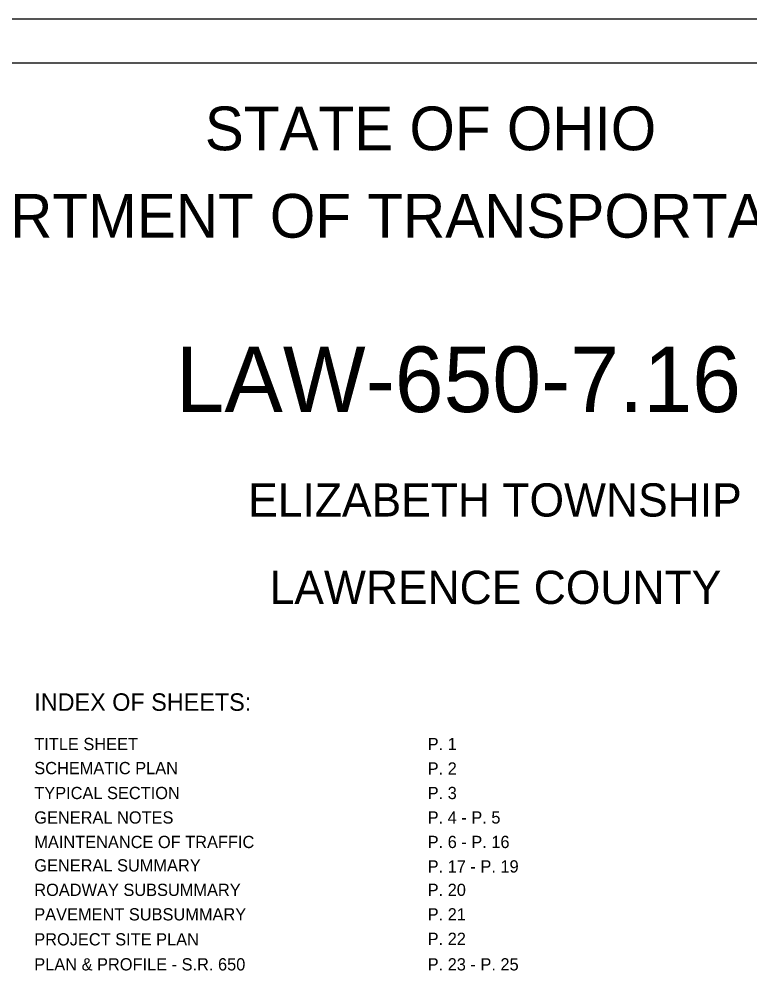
# Model space of a CAD drawing. Extents: x 0 to 44, y -23.8 to 22.
# Drawn here: x 11.67 to 20.03, y 11.07 to 22 of the extents above; entities that cross this region are included whole.
import ezdxf

# ---------------------------------------------------------------- set-up
doc = ezdxf.new("R2010")
doc.units = 0
for name, color, linetype in [('SH_Border', 7, 'Continuous'), ('SH_Cut_Line', 7, 'Continuous'), ('SH_Text', 7, 'Continuous')]:
    doc.layers.add(name, color=color, linetype=linetype)

msp = doc.modelspace()

# ---------------------------------------------------------------- linework, layer by layer
at = {"layer": 'SH_Border'}
msp.add_lwpolyline([(1.5, 21.5), (33.5, 21.5), (33.5, 0.5), (1.5, 0.5)], close=True, dxfattribs=at)
at = {"layer": 'SH_Cut_Line'}
msp.add_lwpolyline([(0, 0), (34, 0), (34, 22), (0, 22)], close=True, dxfattribs=at)

# ---------------------------------------------------------------- texts
at = {"layer": 'SH_Text'}
for s, height, p in [('STATE OF OHIO', 0.5, (13.795, 20.5)), ('DEPARTMENT OF TRANSPORTATION', 0.5, (9.747, 19.5)), ('LAW-650-7.16', 0.75, (13.461, 17.505)), ('ELIZABETH TOWNSHIP', 0.38, (14.29, 16.31)), ('LAWRENCE COUNTY', 0.38, (14.536, 15.31)), ('INDEX OF SHEETS:', 0.2, (11.844, 14.088)), ('TITLE SHEET', 0.14, (11.844, 13.638)), ('P. 1', 0.14, (16.344, 13.638)), ('SCHEMATIC PLAN', 0.14, (11.844, 13.363)), ('P. 2', 0.14, (16.344, 13.358)), ('TYPICAL SECTION', 0.14, (11.844, 13.078)), ('P. 3', 0.14, (16.344, 13.078)), ('GENERAL NOTES', 0.14, (11.844, 12.798)), ('P. 4 - P. 5', 0.14, (16.344, 12.798)), ('MAINTENANCE OF TRAFFIC', 0.14, (11.844, 12.518)), ('P. 6 - P. 16', 0.14, (16.344, 12.518)), ('GENERAL SUMMARY', 0.14, (11.844, 12.25)), ('P. 17 - P. 19', 0.14, (16.344, 12.238)), ('ROADWAY SUBSUMMARY', 0.14, (11.844, 11.97)), ('P. 20', 0.14, (16.344, 11.97)), ('PAVEMENT SUBSUMMARY', 0.14, (11.844, 11.69)), ('P. 21', 0.14, (16.344, 11.69)), ('PROJECT SITE PLAN', 0.14, (11.844, 11.404)), ('P. 22', 0.14, (16.344, 11.41)), ('PLAN & PROFILE - S.R. 650', 0.14, (11.844, 11.118)), ('P. 23 - P. 25', 0.14, (16.344, 11.118))]:
    msp.add_text(s, height=height, dxfattribs=at).set_placement(p)

doc.saveas('drawing.dxf')
